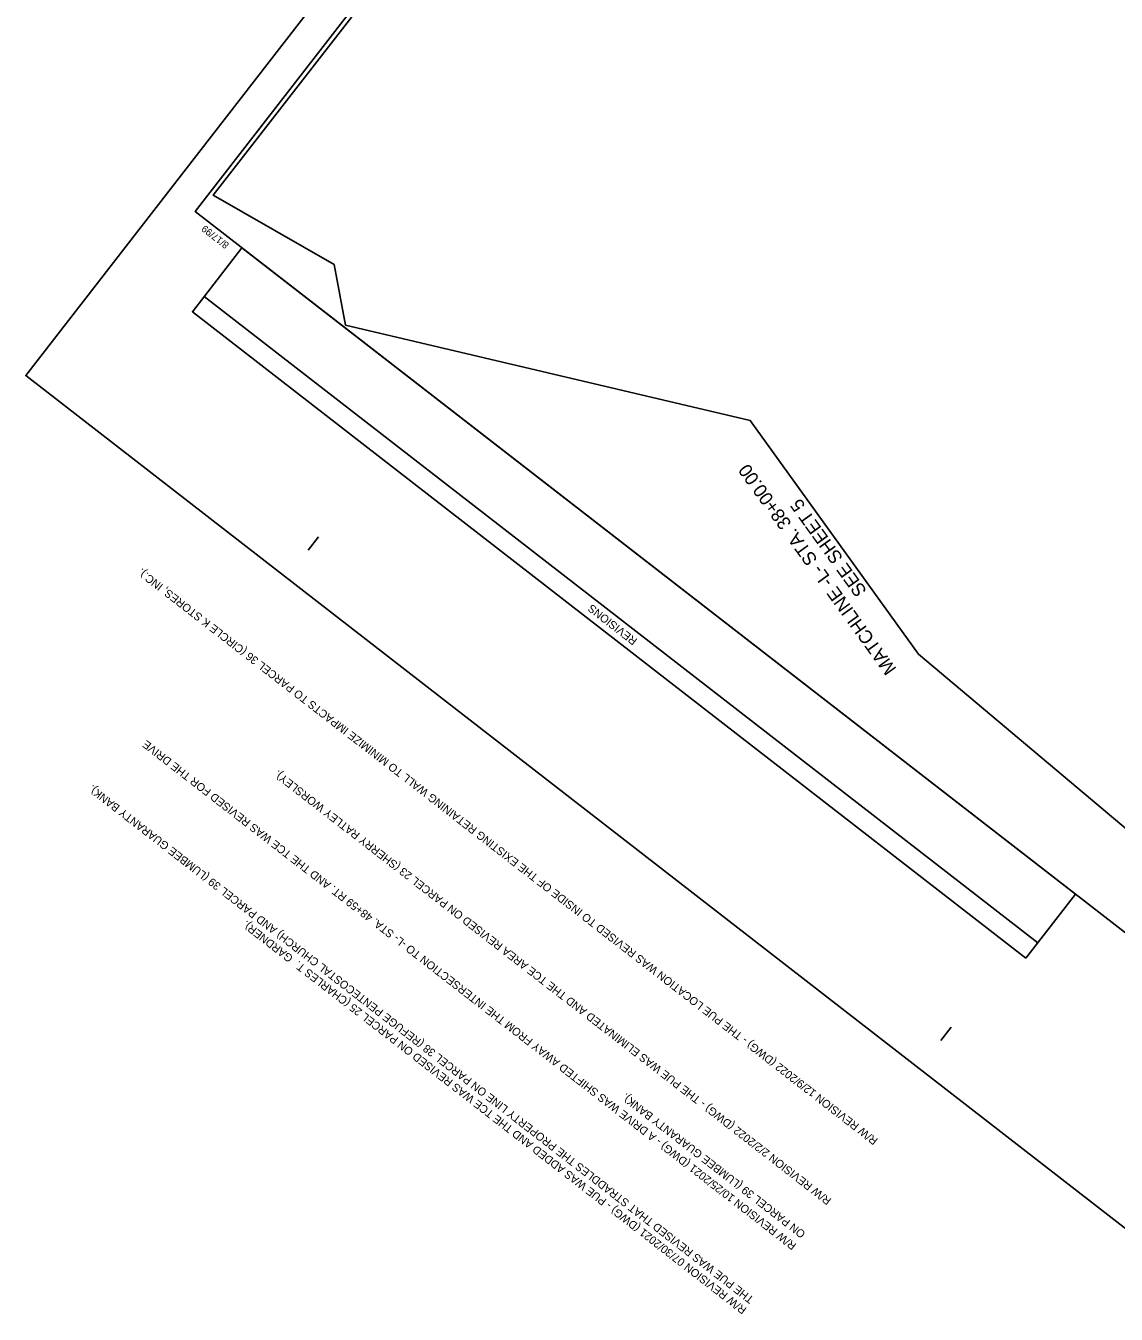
# Model space of a CAD drawing. Extents: x 2013373 to 2015284, y 444589 to 446636.
# Drawn here: x 2013373 to 2014190, y 444589 to 445554 of the extents above; entities that cross this region are included whole.
import ezdxf

# ---------------------------------------------------------------- set-up
doc = ezdxf.new("R2010")
doc.units = 0
for name, color, linetype in [('Matchline', 7, 'Continuous'), ('Matchline Text', 7, 'Continuous'), ('Old_Level_1', 7, 'Continuous'), ('Sheet Block Revision CELL', 7, 'Continuous'), ('Sheet Clip Boundary CELL', 7, 'Continuous'), ('Sheet Plan And Profile CELL', 7, 'Continuous'), ('Sheet Plot Border Outside CELL', 7, 'Continuous')]:
    doc.layers.add(name, color=color, linetype=linetype)

msp = doc.modelspace()

# ---------------------------------------------------------------- linework, layer by layer
at = {"layer": 'Matchline'}
msp.add_line((2014041.96, 445083.42), (2013915.76, 445258.44), dxfattribs=at)
at = {"layer": 'Sheet Block Revision CELL'}
msp.add_line((2014131.31, 444867.05), (2013506.53, 445351.59), dxfattribs=at)
msp.add_lwpolyline([(2014122.39, 444855.55), (2013497.61, 445340.09), (2013534.72, 445387.94), (2014159.5, 444903.4)], close=True, dxfattribs=at)
at = {"layer": 'Sheet Clip Boundary CELL'}
msp.add_lwpolyline([(2014175.88, 446280.17), (2013513.08, 445427.57), (2013603.78, 445375.37), (2013612.37, 445329.9), (2013915.76, 445258.44), (2014041.96, 445083.42), (2014361.11, 444814.86), (2015247.44, 445957.73), (2014564.17, 446487.44), (2014441.59, 446328.91), (2014350.55, 446399.68), (2014226.85, 446240.55)], close=True, dxfattribs=at)
at = {"layer": 'Sheet Plan And Profile CELL'}
for p, q in [((2013584.49, 445161.42), (2013592.15, 445171.29)), ((2014058.62, 444793.71), (2014066.28, 444803.59))]:
    msp.add_line(p, q, dxfattribs=at)
msp.add_lwpolyline([(2014418.93, 446600.43), (2013499.68, 445415.12), (2014329.4, 444771.64), (2015248.65, 445956.96)], close=True, dxfattribs=at)
at = {"layer": 'Sheet Plot Border Outside CELL'}
msp.add_lwpolyline([(2014241.91, 444618.03), (2015283.73, 445961.39), (2014414.5, 446635.51), (2013372.67, 445292.15)], close=True, dxfattribs=at)

# ---------------------------------------------------------------- texts
at = {"layer": 'Matchline Text'}
for s, p in [('MATCHLINE -L- STA. 38+00.00', (2014025.76, 445072.32)), ('SEE SHEET 5', (2014003.55, 445130.91))]:
    msp.add_text(s, height=10, rotation=125.79448, dxfattribs=at).set_placement(p)
at = {"layer": 'Old_Level_1'}
for s, p in [('R/W REVISION 12/9/2022 (DWG) - THE PUE LOCATION WAS REVISED TO INSIDE OF THE EXISTING RETAINING WALL TO MINIMIZE IMPACTS TO PARCEL 36 (CIRCLE K STORES, INC.).', (2014011.94, 444719.68)), ('R/W REVISION 10/25/2021 (DWG) - A DRIVE WAS SHIFTED AWAY FROM THE INTERSECTION TO -L- STA. 48+59 RT. AND THE TCE WAS REVISED FOR THE DRIVE', (2013950.88, 444640.95)), ('R/W REVISION 2/2/2022 (DWG) - THE PUE WAS ELIMINATED AND THE TCE AREA REVISED ON PARCEL 23 (SHERRY RATLEY WORSLEY).', (2013977.05, 444674.7)), ('THE PUE WAS REVISED THAT STRADDLES THE PROPERTY LINE ON PARCEL 38 (REFUGE PENTECOSTAL CHURCH) AND PARCEL 39 (LUMBEE GUARANTY BANK). ', (2013918.96, 444600.78)), ('R/W REVISION 07/30/2021 (DWG) - PUE WAS ADDED AND THE TCE WAS REVISED ON PARCEL 25 (CHARLES T.  GARDNER). ', (2013913.57, 444592.84)), ('ON PARCEL 39 (LUMBEE GUARANTY BANK).', (2013957.67, 444649.71))]:
    msp.add_text(s, height=6, rotation=142.2051, dxfattribs=at).set_placement(p)
at = {"layer": 'Sheet Block Revision CELL'}
msp.add_text('REVISIONS', height=6, rotation=142.2051, dxfattribs=at).set_placement((2013831.59, 445094.37))
at = {"layer": 'Sheet Plan And Profile CELL'}
msp.add_text('8/17/99', height=5.25, rotation=142.2051, dxfattribs=at).set_placement((2013525.5, 445390.98))

doc.saveas('drawing.dxf')
